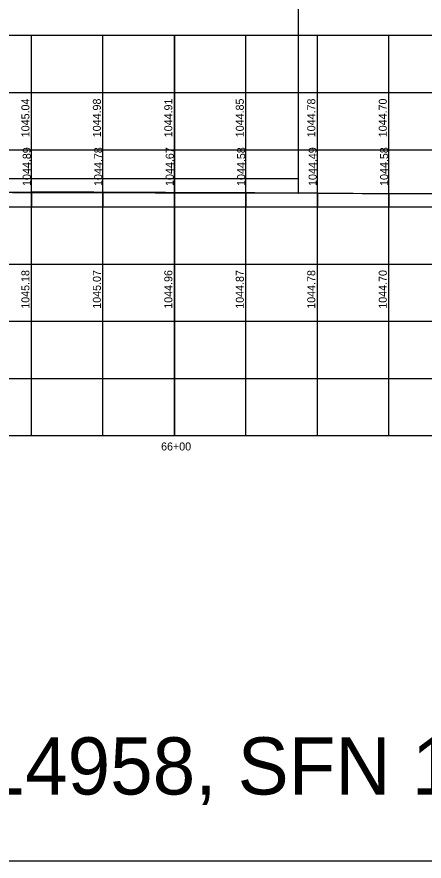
# Model space of a CAD drawing. Extents: x -2222 to 2066, y -217 to 964.
# Drawn here: x -1574.9 to -1432.5, y -217 to 78.3 of the extents above; entities that cross this region are included whole.
import ezdxf

# ---------------------------------------------------------------- set-up
doc = ezdxf.new("R2010")
doc.units = 0
for name, color, linetype in [('PF_X_Ground_Line', 7, 'Continuous'), ('SC_Scratch1', 7, 'Continuous'), ('SC_Scratch2', 7, 'Continuous'), ('SC_Scratch3', 7, 'Continuous'), ('XS_P_Pavt_Surface', 7, 'Continuous')]:
    doc.layers.add(name, color=color, linetype=linetype)

msp = doc.modelspace()

# ---------------------------------------------------------------- linework, layer by layer
at = {"layer": 'PF_X_Ground_Line'}
msp.add_line((-1719.84, 17.73), (-1569.84, 17.04), dxfattribs=at)
for centre, radius, start, end in [((-978249.19, -221977800.17), 221979965.85, 89.74789324, 89.7479061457), ((-4862336.85, -1350237348.28), 1350246114.48, 89.79373555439, 89.79373767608), ((-1257.34, 62517.31), 62501.03, 269.8051954, 269.8510315)]:
    msp.add_arc(centre, radius, start, end, dxfattribs=at)
at = {"layer": 'SC_Scratch1'}
for p, q in [((-1394.84, 71.86), (-1844.84, 71.86)), ((-1569.84, -68.14), (-1569.84, 71.86)), ((-1544.84, -68.14), (-1544.84, 71.86)), ((-1519.84, -68.14), (-1519.84, 71.86)), ((-1494.84, -68.14), (-1494.84, 71.86)), ((-1469.84, -68.14), (-1469.84, 71.86)), ((-1444.84, -68.14), (-1444.84, 71.86)), ((-1844.84, 51.86), (-1394.84, 51.86)), ((-1844.84, 31.86), (-1394.84, 31.86)), ((-1476.47, 16.54), (-1476.47, 26.74)), ((-1601.47, 21.79), (-1476.47, 21.79)), ((-1844.84, 11.86), (-1394.84, 11.86)), ((-1844.84, -8.14), (-1394.84, -8.14)), ((-1844.84, -28.14), (-1394.84, -28.14)), ((-1844.84, -48.14), (-1394.84, -48.14)), ((-1844.84, -68.14), (-1394.84, -68.14))]:
    msp.add_line(p, q, dxfattribs=at)
msp.add_lwpolyline([(-2065.36, 217.02), (-1167.31, 217.02), (-1167.31, -217.02), (-2065.36, -217.02)], close=True, dxfattribs=at)
at = {"layer": 'SC_Scratch2'}
for p, q in [((-1569.84, 11.86), (-1569.84, 16.9)), ((-1544.84, 11.86), (-1544.84, 16.84)), ((-1519.84, 11.86), (-1519.84, 16.78)), ((-1494.84, 11.86), (-1494.84, 16.71)), ((-1469.84, 11.86), (-1469.84, 16.64)), ((-1444.84, 11.86), (-1444.84, 16.56))]:
    msp.add_line(p, q, dxfattribs=at)
at = {"layer": 'SC_Scratch3'}
for p, q in [((-1476.47, 16.67), (-1476.47, 926.77)), ((-1519.84, 71.86), (-1519.84, -68.14)), ((-1569.84, 17.04), (-1569.84, 11.86)), ((-1544.84, 16.93), (-1544.84, 11.86)), ((-1519.84, 16.82), (-1519.84, 11.86)), ((-1494.84, 16.73), (-1494.84, 11.86)), ((-1469.84, 16.64), (-1469.84, 11.86)), ((-1444.84, 16.56), (-1444.84, 11.86))]:
    msp.add_line(p, q, dxfattribs=at)
at = {"layer": 'XS_P_Pavt_Surface'}
msp.add_lwpolyline([(-1601.47, 16.98), (-1476.47, 16.67), (-1476.47, 16.52), (-1576.47, 16.77)], dxfattribs=at)

# ---------------------------------------------------------------- texts
at = {"layer": 'SC_Scratch1'}
for s, p in [('1045.04', (-1570.56, 36.21)), ('1044.98', (-1545.56, 36.21)), ('1044.91', (-1520.56, 36.21)), ('1044.85', (-1495.56, 36.21)), ('1044.78', (-1470.56, 36.21)), ('1044.70', (-1445.56, 36.22)), ('1044.89', (-1570.09, 19.18)), ('1044.78', (-1545.09, 19.18)), ('1044.67', (-1520.09, 19.18)), ('1044.58', (-1495.09, 19.18)), ('1044.49', (-1470.09, 19.18)), ('1044.58', (-1445.09, 19.19)), ('1045.18', (-1570.56, -23.79)), ('1045.07', (-1545.56, -23.79)), ('1044.96', (-1520.56, -23.79)), ('1044.87', (-1495.56, -23.79)), ('1044.78', (-1470.56, -23.79)), ('1044.70', (-1445.56, -23.78))]:
    msp.add_text(s, height=2.8, rotation=90, dxfattribs=at).set_placement(p)
for s, height, p in [('66+00', 2.8, (-1524.5, -73.36)), ('REF: PID 114958, SFN 1102648 PROFILE', 20, (-1722.17, -193.72))]:
    msp.add_text(s, height=height, dxfattribs=at).set_placement(p)

doc.saveas('drawing.dxf')
